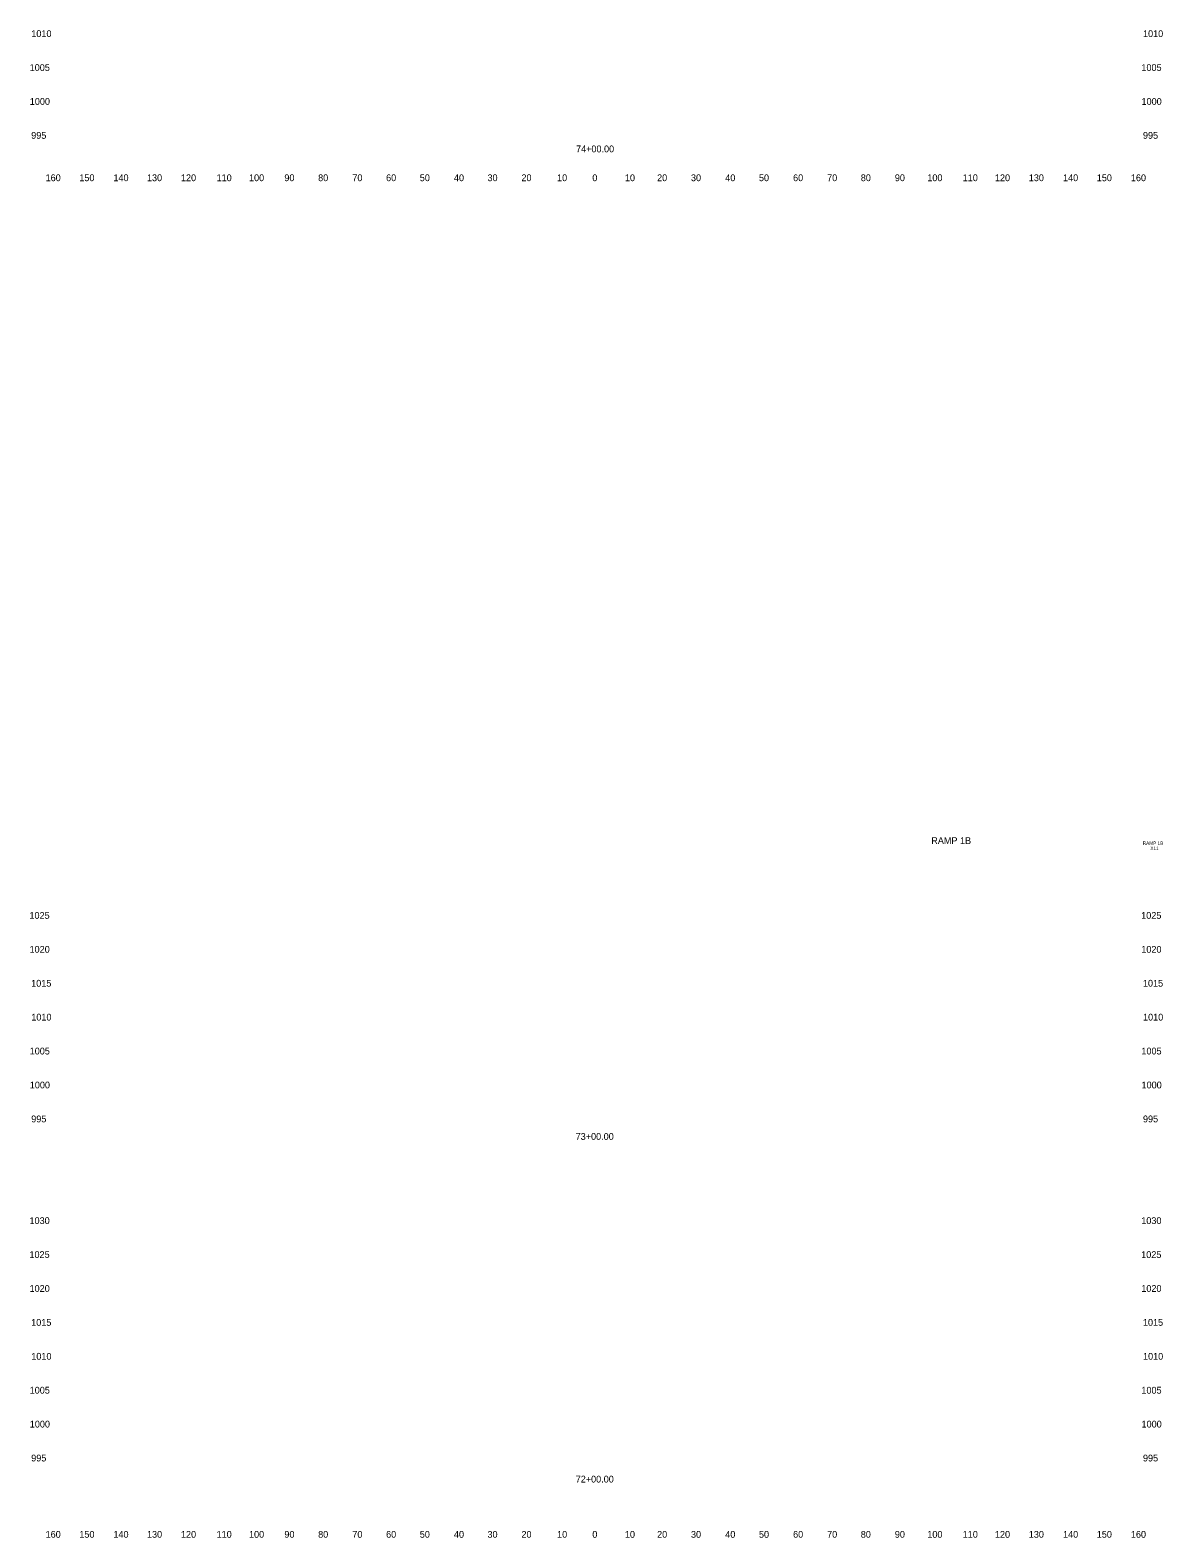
# Model space of a CAD drawing. Extents: x 4994 to 5843, y 4997 to 8804.
# Drawn here: x 5508.5 to 5842.5, y 4997.5 to 5442 of the extents above; entities that cross this region are included whole.
import ezdxf

# ---------------------------------------------------------------- set-up
doc = ezdxf.new("R2010")
doc.units = 0
for name, color, linetype in [('CLS_Search_Dist', 7, 'Continuous'), ('RD_XE_Ground', 7, 'Continuous'), ('UC_PD_Text', 7, 'Continuous')]:
    doc.layers.add(name, color=color, linetype=linetype)

msp = doc.modelspace()

# ---------------------------------------------------------------- texts
at = {"layer": 'CLS_Search_Dist'}
for s, p in [('1010', (5508.88, 5440)), ('1010', (5836.68, 5440)), ('1005', (5508.4, 5430)), ('1005', (5836.2, 5430)), ('1000', (5508.44, 5420)), ('1000', (5836.24, 5420)), ('995', (5508.86, 5410)), ('995', (5836.66, 5410)), ('160', (5513.1, 5397.5)), ('150', (5523.04, 5397.5)), ('140', (5533.1, 5397.5)), ('130', (5542.99, 5397.5)), ('120', (5553.01, 5397.5)), ('110', (5563.51, 5397.5)), ('100', (5573.07, 5397.5)), ('90', (5583.5, 5397.5)), ('80', (5593.46, 5397.5)), ('70', (5603.54, 5397.5)), ('60', (5613.5, 5397.5)), ('50', (5623.43, 5397.5)), ('40', (5633.5, 5397.5)), ('30', (5643.39, 5397.5)), ('20', (5653.4, 5397.5)), ('10', (5663.91, 5397.5)), ('0', (5674.3, 5397.5)), ('0', (5674.3, 5397.5)), ('10', (5683.91, 5397.5)), ('20', (5693.4, 5397.5)), ('30', (5703.39, 5397.5)), ('40', (5713.5, 5397.5)), ('50', (5723.43, 5397.5)), ('60', (5733.5, 5397.5)), ('70', (5743.54, 5397.5)), ('80', (5753.46, 5397.5)), ('90', (5763.5, 5397.5)), ('100', (5773.07, 5397.5)), ('110', (5783.51, 5397.5)), ('120', (5793.01, 5397.5)), ('130', (5802.99, 5397.5)), ('140', (5813.1, 5397.5)), ('150', (5823.04, 5397.5)), ('160', (5833.1, 5397.5)), ('1025', (5508.34, 5180)), ('1025', (5836.14, 5180)), ('1020', (5508.37, 5170)), ('1020', (5836.17, 5170)), ('1015', (5508.85, 5160)), ('1015', (5836.65, 5160)), ('1010', (5508.88, 5150)), ('1010', (5836.68, 5150)), ('1005', (5508.4, 5140)), ('1005', (5836.2, 5140)), ('1000', (5508.44, 5130)), ('1000', (5836.24, 5130)), ('995', (5508.86, 5120)), ('995', (5836.66, 5120)), ('1030', (5508.36, 5090)), ('1030', (5836.16, 5090)), ('1025', (5508.34, 5080)), ('1025', (5836.14, 5080)), ('1020', (5508.37, 5070)), ('1020', (5836.17, 5070)), ('1015', (5508.85, 5060)), ('1015', (5836.65, 5060)), ('1010', (5508.88, 5050)), ('1010', (5836.68, 5050)), ('1005', (5508.4, 5040)), ('1005', (5836.2, 5040)), ('1000', (5508.44, 5030)), ('1000', (5836.24, 5030)), ('995', (5508.86, 5020)), ('995', (5836.66, 5020)), ('160', (5513.1, 4997.5)), ('150', (5523.04, 4997.5)), ('140', (5533.1, 4997.5)), ('130', (5542.99, 4997.5)), ('120', (5553.01, 4997.5)), ('110', (5563.51, 4997.5)), ('100', (5573.07, 4997.5)), ('90', (5583.5, 4997.5)), ('80', (5593.46, 4997.5)), ('70', (5603.54, 4997.5)), ('60', (5613.5, 4997.5)), ('50', (5623.43, 4997.5)), ('40', (5633.5, 4997.5)), ('30', (5643.39, 4997.5)), ('20', (5653.4, 4997.5)), ('10', (5663.91, 4997.5)), ('0', (5674.3, 4997.5)), ('0', (5674.3, 4997.5)), ('10', (5683.91, 4997.5)), ('20', (5693.4, 4997.5)), ('30', (5703.39, 4997.5)), ('40', (5713.5, 4997.5)), ('50', (5723.43, 4997.5)), ('60', (5733.5, 4997.5)), ('70', (5743.54, 4997.5)), ('80', (5753.46, 4997.5)), ('90', (5763.5, 4997.5)), ('100', (5773.07, 4997.5)), ('110', (5783.51, 4997.5)), ('120', (5793.01, 4997.5)), ('130', (5802.99, 4997.5)), ('140', (5813.1, 4997.5)), ('150', (5823.04, 4997.5)), ('160', (5833.1, 4997.5))]:
    msp.add_text(s, height=2, dxfattribs=at).set_placement(p)
at = {"layer": 'RD_XE_Ground'}
for s, p in [('74+00.00', (5669.5, 5406.02)), ('73+00.00', (5669.39, 5114.82)), ('72+00.00', (5669.4, 5013.78))]:
    msp.add_text(s, height=2, dxfattribs=at).set_placement(p)
at = {"layer": 'UC_PD_Text'}
for s, height, p in [('RAMP 1B', 2, (5774.24, 5202.06)), ('RAMP 1B', 1, (5836.59, 5201.8)), ('X11', 1, (5838.85, 5200.3))]:
    msp.add_text(s, height=height, dxfattribs=at).set_placement(p)

doc.saveas('drawing.dxf')
